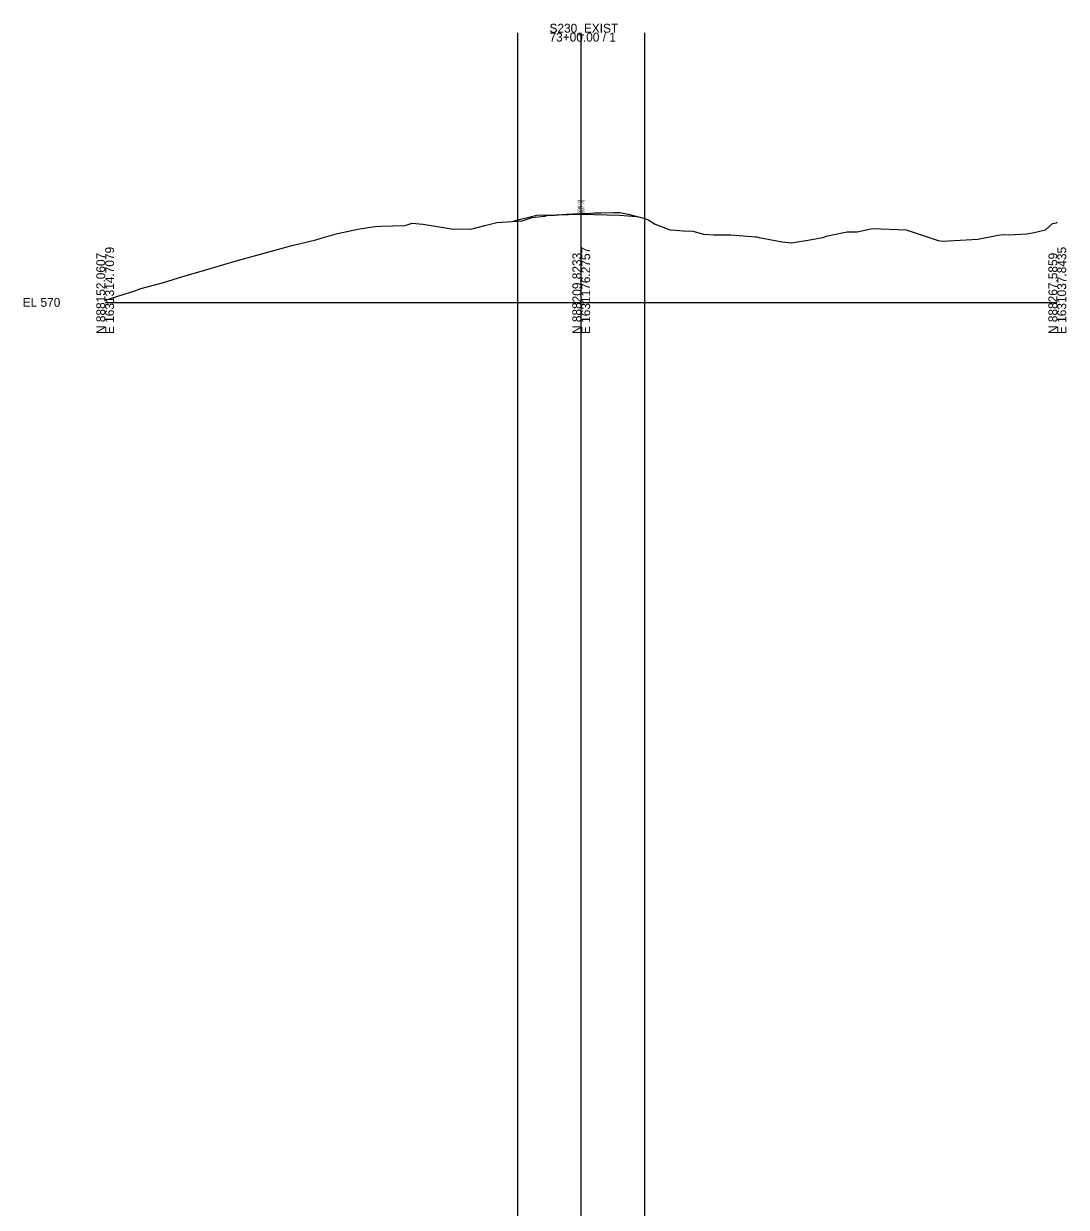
# Model space of a CAD drawing. Extents: x 1631115 to 1631443, y 885974 to 892071.
# Drawn here: x 1631114.8 to 1631443.3, y 891698.4 to 892071.5 of the extents above; entities that cross this region are included whole.
import ezdxf

# ---------------------------------------------------------------- set-up
doc = ezdxf.new("R2010")
doc.units = 0
for name, color, linetype in [('Default', 7, 'Continuous'), ('RD_GPK_XS_Cell', 7, 'Continuous'), ('RD_XS_EarthShd', 7, 'Continuous'), ('RD_XS_ExGround', 7, 'Continuous'), ('RD_XS_Pave', 7, 'Continuous'), ('RD_XS_TieSlope', 7, 'Continuous'), ('RD_XS_TX_Elev_EX', 7, 'Continuous'), ('RD_XS_TX_Elev_PR', 7, 'Continuous')]:
    doc.layers.add(name, color=color, linetype=linetype)

msp = doc.modelspace()

# ---------------------------------------------------------------- linework, layer by layer
at = {"layer": 'Default'}
for p, q in [((1631270.47, 885983.65), (1631270.47, 892068.63)), ((1631290.47, 885983.65), (1631290.47, 892068.63)), ((1631310.47, 885983.65), (1631310.47, 892068.63))]:
    msp.add_line(p, q, dxfattribs=at)
at = {"layer": 'RD_GPK_XS_Cell'}
for p, q in [((1631290.47, 891983.65), (1631290.47, 892068.63)), ((1631140.47, 891983.65), (1631290.47, 891983.65)), ((1631290.47, 891983.65), (1631440.47, 891983.65))]:
    msp.add_line(p, q, dxfattribs=at)
at = {"layer": 'RD_XS_EarthShd'}
for p, q in [((1631278.47, 892011.17), (1631276.47, 892011.01)), ((1631302.47, 892011.17), (1631307.79, 892010.74))]:
    msp.add_line(p, q, dxfattribs=at)
at = {"layer": 'RD_XS_ExGround'}
msp.add_lwpolyline([(1631140.47, 891984.38), (1631150.13, 891987.42), (1631150.85, 891987.73), (1631151.68, 891987.99), (1631158.56, 891989.84), (1631163.56, 891991.41), (1631165.7, 891992.04), (1631166.73, 891992.29), (1631172.17, 891993.86), (1631178.92, 891995.87), (1631182.13, 891996.86), (1631197.82, 892001.16), (1631198.51, 892001.36), (1631198.86, 892001.43), (1631206.89, 892003.34), (1631208.49, 892003.9), (1631213.7, 892005.38), (1631220.61, 892006.84), (1631222.06, 892007.06), (1631224.65, 892007.42), (1631225.62, 892007.54), (1631227.35, 892007.61), (1631234.91, 892007.91), (1631235.98, 892008.21), (1631237.18, 892008.56), (1631240.51, 892008.33), (1631248.93, 892006.91), (1631249.49, 892006.85), (1631255.71, 892006.71), (1631260.14, 892007.88), (1631263.85, 892008.81), (1631271.88, 892009.38), (1631275, 892010.34), (1631276.89, 892010.6), (1631278.86, 892010.85), (1631279.69, 892010.97), (1631282.02, 892011.15), (1631285.81, 892011.43), (1631290.07, 892011.66), (1631290.47, 892011.68), (1631293.42, 892011.8), (1631294.62, 892011.83), (1631296.59, 892011.9), (1631300.65, 892011.93), (1631302.62, 892011.98), (1631305.3, 892011.39), (1631310.47, 892010.05), (1631311.81, 892009.52), (1631313.74, 892008.26), (1631318.41, 892006.53), (1631320.15, 892006.38), (1631322.71, 892006.22), (1631325.61, 892006.08), (1631329.04, 892005.12), (1631332.35, 892004.9), (1631337.61, 892004.88), (1631345.34, 892004.31), (1631345.82, 892004.25), (1631346.48, 892004.13), (1631353.74, 892002.71), (1631356.73, 892002.45), (1631363.12, 892003.41), (1631366.56, 892004.11), (1631368.06, 892004.57), (1631374.27, 892005.83), (1631377.37, 892005.87), (1631382.21, 892006.95), (1631392.84, 892006.48), (1631402.97, 892003.15), (1631404.29, 892002.95), (1631415.44, 892003.51), (1631421.8, 892004.84), (1631423.44, 892005), (1631425.27, 892004.96), (1631430.72, 892005.24), (1631433.2, 892005.66), (1631436.77, 892006.51), (1631438.99, 892008.46), (1631440.2, 892008.67), (1631440.47, 892008.88)], dxfattribs=at)
at = {"layer": 'RD_XS_Pave'}
for p, q in [((1631278.47, 892011.17), (1631290.47, 892011.41)), ((1631290.47, 892011.41), (1631302.47, 892011.17))]:
    msp.add_line(p, q, dxfattribs=at)
at = {"layer": 'RD_XS_TieSlope'}
msp.add_line((1631276.47, 892011.01), (1631269.22, 892009.19), dxfattribs=at)

# ---------------------------------------------------------------- texts
at = {"layer": 'RD_GPK_XS_Cell'}
for s, p in [('S230_EXIST', (1631280.47, 892068.63)), ('73+00.00 / 1', (1631280.47, 892065.83)), ('EL 570', (1631114.47, 891982.25))]:
    msp.add_text(s, height=2.8, dxfattribs=at).set_placement(p)
for s, p in [('N 888152.0607', (1631140.47, 891973.65)), ('E 1631314.7079', (1631143.27, 891973.65)), ('N 888209.8233', (1631290.47, 891973.65)), ('E 1631176.2757', (1631293.27, 891973.65)), ('N 888267.5859', (1631440.47, 891973.65)), ('E 1631037.8435', (1631443.27, 891973.65))]:
    msp.add_text(s, height=2.8, rotation=90, dxfattribs=at).set_placement(p)
at = {"layer": 'RD_XS_TX_Elev_EX'}
msp.add_text('598.03', height=1, rotation=90, dxfattribs=at).set_placement((1631290.37, 892011.78))
at = {"layer": 'RD_XS_TX_Elev_PR'}
msp.add_text(' 597.76', height=1, rotation=90, dxfattribs=at).set_placement((1631291.47, 892011.41))

doc.saveas('drawing.dxf')
